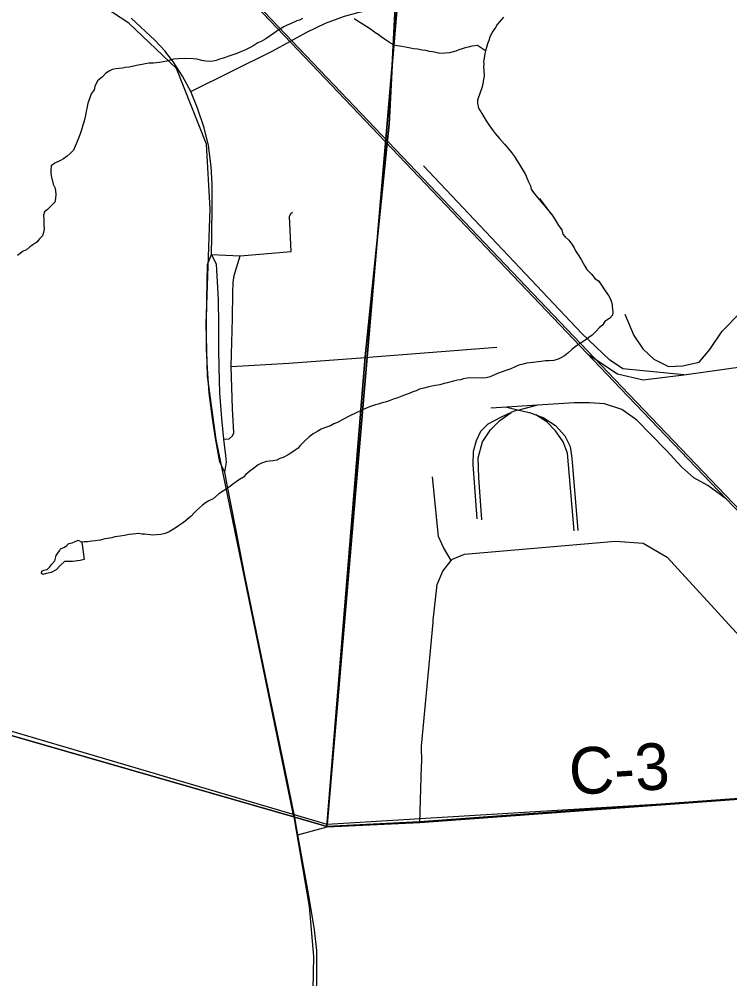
# Model space of a CAD drawing. Extents: x 0 to 34, y 0 to 22.
# Drawn here: x 13.591 to 14.456, y 14.81 to 15.978 of the extents above; entities that cross this region are included whole.
import ezdxf

# ---------------------------------------------------------------- set-up
doc = ezdxf.new("R2010")
doc.units = 0
for name, color, linetype in [('GM_X_City_Street', 7, 'Continuous'), ('GM_X_County_Road', 7, 'Continuous'), ('GM_X_County_Road_Text', 7, 'Continuous'), ('GM_X_Minor_River', 7, 'Continuous'), ('GM_X_Rail_Line', 7, 'Continuous'), ('GM_X_Section', 7, 'Continuous'), ('GM_X_State_Route', 7, 'Continuous'), ('GM_X_Township_Road', 7, 'Continuous'), ('SC_Scratch1', 7, 'Continuous'), ('SH_Cut_Line', 7, 'Continuous')]:
    doc.layers.add(name, color=color, linetype=linetype)

msp = doc.modelspace()

# ---------------------------------------------------------------- linework, layer by layer
at = {"layer": 'GM_X_City_Street'}
for points in [[(13.8248, 15.6914), (13.8596, 15.6897), (13.9219, 15.6948), (13.9199, 15.7377), (13.9214, 15.7411), (13.9234, 15.743)], [(13.84, 15.4669), (13.8462, 15.4673), (13.8503, 15.4706), (13.8521, 15.4746), (13.8503, 15.5039), (13.8489, 15.5549), (13.8506, 15.6134), (13.8507, 15.6453), (13.8514, 15.6574), (13.8526, 15.666), (13.8596, 15.6897)]]:
    msp.add_lwpolyline(points, dxfattribs=at)
at = {"layer": 'GM_X_County_Road'}
msp.add_line((13.9301, 14.9855), (13.9655, 14.995), dxfattribs=at)
for points in [[(13.8997, 15.939), (13.941, 15.9618), (13.9637, 15.9729), (13.9868, 15.9812), (14.0046, 15.9861), (14.0169, 15.9886), (14.0308, 15.9904), (14.0486, 15.9922), (14.137, 15.9987), (14.2945, 16.0126), (14.3436, 16.017)], [(13.7996, 15.8897), (13.8988, 15.9385), (13.8997, 15.939)], [(13.9655, 14.995), (14.0785, 15.0005), (14.5056, 15.0318), (14.9883, 15.0618)]]:
    msp.add_lwpolyline(points, dxfattribs=at)
at = {"layer": 'GM_X_Minor_River'}
for points in [[(13.9355, 15.9783), (13.932, 15.9765), (13.9286, 15.9755), (13.922, 15.9723), (13.917, 15.9705), (13.9128, 15.9684), (13.9062, 15.9644), (13.9016, 15.9611), (13.8965, 15.9575), (13.8911, 15.9538), (13.8853, 15.9506), (13.8811, 15.9488), (13.8764, 15.9455), (13.8726, 15.9437), (13.8656, 15.9398), (13.8614, 15.9384), (13.8556, 15.9359), (13.8521, 15.9345), (13.8483, 15.9335), (13.8449, 15.9324), (13.8406, 15.9307), (13.8345, 15.9289), (13.8307, 15.9275), (13.8268, 15.9265), (13.823, 15.9263), (13.8181, 15.9264), (13.8132, 15.9273), (13.8071, 15.929), (13.8026, 15.9295), (13.7916, 15.9299), (13.784, 15.9293), (13.7786, 15.9288), (13.7706, 15.9267), (13.7614, 15.9251), (13.7542, 15.9242), (13.7488, 15.924), (13.7442, 15.9233), (13.7404, 15.9223), (13.7355, 15.9217), (13.7301, 15.9203), (13.7248, 15.9194), (13.7198, 15.9188), (13.7164, 15.9181), (13.7121, 15.9175), (13.7083, 15.9172), (13.7041, 15.9162), (13.7003, 15.9144), (13.6964, 15.9119), (13.6921, 15.9074), (13.6863, 15.9027), (13.683, 15.8959), (13.6821, 15.8918), (13.6786, 15.8869), (13.6765, 15.8809), (13.6744, 15.8753)], [(14.1586, 15.9392), (14.1489, 15.9456), (14.1417, 15.9446), (14.1375, 15.9436), (14.1336, 15.9426), (14.1302, 15.9416), (14.126, 15.9402), (14.1225, 15.9388), (14.1148, 15.9367), (14.1095, 15.9361), (14.103, 15.9359), (14.0981, 15.9369), (14.094, 15.9377), (14.0902, 15.9382), (14.086, 15.9395), (14.0815, 15.94), (14.0758, 15.941), (14.0709, 15.9415), (14.0671, 15.9424), (14.0611, 15.9437), (14.0565, 15.9442), (14.0509, 15.9451), (14.0475, 15.946), (14.0426, 15.9484), (14.0355, 15.9532), (14.0314, 15.956), (14.0277, 15.9588), (14.0236, 15.9616), (14.0195, 15.9647), (14.0139, 15.9683), (14.0064, 15.9731), (14.002, 15.9759), (13.9986, 15.9779)], [(14.1803, 15.98), (14.1756, 15.9744), (14.1725, 15.9711), (14.1705, 15.9673), (14.1665, 15.9618), (14.1637, 15.9558), (14.1624, 15.9516), (14.1608, 15.9475), (14.1595, 15.943), (14.1586, 15.9392), (14.1578, 15.9358), (14.1568, 15.9301), (14.156, 15.9263), (14.1563, 15.9229), (14.1561, 15.9191), (14.1564, 15.9157), (14.157, 15.9081), (14.1557, 15.9024), (14.1552, 15.8986), (14.1539, 15.8941), (14.1518, 15.8885), (14.1506, 15.8847), (14.1489, 15.8794), (14.1488, 15.8756), (14.1501, 15.8695), (14.1541, 15.8629), (14.1563, 15.859), (14.1592, 15.854), (14.1625, 15.849), (14.1665, 15.8435), (14.1701, 15.8385), (14.1753, 15.8326), (14.1815, 15.8256), (14.1863, 15.8197), (14.19, 15.8154), (14.1936, 15.8104), (14.1962, 15.8065), (14.1991, 15.8022), (14.2016, 15.798), (14.2071, 15.7887), (14.2089, 15.7848), (14.2106, 15.7798), (14.2131, 15.7748), (14.2142, 15.771), (14.2178, 15.7655), (14.2387, 15.7406), (14.2244, 15.7595)], [(13.6744, 15.8753), (13.6736, 15.8711), (13.6722, 15.8651), (13.6714, 15.8609), (13.6705, 15.8568), (13.6696, 15.8522), (13.6683, 15.8485), (13.6671, 15.8443), (13.665, 15.8383), (13.6638, 15.8349), (13.6605, 15.8267), (13.6589, 15.8233), (13.6568, 15.8184), (13.6529, 15.8144), (13.649, 15.811), (13.6447, 15.8078), (13.6401, 15.8052), (13.6343, 15.8024), (13.6296, 15.7991), (13.6291, 15.7942), (13.6294, 15.79), (13.63, 15.7854), (13.632, 15.777), (13.6346, 15.7719), (13.6355, 15.7647), (13.635, 15.7594), (13.6341, 15.7552), (13.6294, 15.7501), (13.6251, 15.746), (13.6216, 15.7431), (13.6203, 15.7393), (13.6209, 15.7336), (13.6207, 15.7271), (13.621, 15.7226), (13.6204, 15.718), (13.6192, 15.7142), (13.6157, 15.7102), (13.6121, 15.7065), (13.6036, 15.7007), (13.5997, 15.697), (13.5958, 15.6952), (13.5888, 15.6901)], [(14.2387, 15.7406), (14.242, 15.7355), (14.2446, 15.7313), (14.2475, 15.7266), (14.2515, 15.7212), (14.2525, 15.7162), (14.2554, 15.7127), (14.2599, 15.7087), (14.2635, 15.7041), (14.2664, 15.6994), (14.2682, 15.6959), (14.2704, 15.6921), (14.2748, 15.6851), (14.2773, 15.6808), (14.2795, 15.677), (14.282, 15.6731), (14.2875, 15.6676), (14.2919, 15.6618), (14.296, 15.6594), (14.2997, 15.6539), (14.3041, 15.6473), (14.3081, 15.6415), (14.3103, 15.638), (14.3124, 15.6326), (14.3129, 15.625), (14.3136, 15.6212), (14.3131, 15.6174), (14.3099, 15.6137), (14.3037, 15.6097), (14.3009, 15.6052), (14.2974, 15.6027), (14.2927, 15.5975), (14.2884, 15.5934), (14.2842, 15.5905), (14.2783, 15.5861), (14.2729, 15.5825), (14.2694, 15.5803), (14.2636, 15.5756), (14.2585, 15.5712), (14.2546, 15.5682), (14.2511, 15.5661), (14.2469, 15.5639), (14.2415, 15.5625), (14.2358, 15.562), (14.2313, 15.5621), (14.2263, 15.5611), (14.2229, 15.5608), (14.216, 15.5599), (14.2126, 15.5596), (14.2087, 15.559), (14.2042, 15.558), (14.1992, 15.5566), (14.1946, 15.5545), (14.1892, 15.5524), (14.1846, 15.5506), (14.18, 15.5492), (14.175, 15.5475), (14.1696, 15.545), (14.1642, 15.5425), (14.1592, 15.5415), (14.1542, 15.5409), (14.1394, 15.5413), (14.136, 15.5411), (14.1318, 15.54), (14.128, 15.539), (14.1245, 15.5384), (14.118, 15.5367), (14.1123, 15.5353), (14.1081, 15.5343), (14.1027, 15.5329), (14.0977, 15.532), (14.0931, 15.531), (14.0893, 15.5303), (14.0832, 15.5286), (14.0782, 15.5276), (14.074, 15.5255), (14.0698, 15.5241), (14.0655, 15.5223), (14.0617, 15.5209), (14.0567, 15.5191), (14.0505, 15.5167), (14.0471, 15.5156), (14.0413, 15.5135), (14.0379, 15.5121), (14.0325, 15.5108), (14.0279, 15.5094), (14.0245, 15.5083), (14.021, 15.5073), (14.0172, 15.5059), (14.0087, 15.5024), (14.0018, 15.4992), (13.9925, 15.4945), (13.9856, 15.4909), (13.979, 15.4873), (13.974, 15.4852), (13.9697, 15.483), (13.9624, 15.4806), (13.9582, 15.4788), (13.9543, 15.4763), (13.9485, 15.473), (13.9439, 15.4694)], [(13.9439, 15.4694), (13.938, 15.4642), (13.9329, 15.4591), (13.9302, 15.4557), (13.9267, 15.4532), (13.9228, 15.4506), (13.9182, 15.4477), (13.912, 15.4445), (13.9081, 15.4431), (13.9043, 15.4413), (13.9001, 15.4403), (13.8955, 15.44), (13.8917, 15.4394), (13.8856, 15.4377), (13.8817, 15.4355), (13.8759, 15.4311), (13.8716, 15.4278), (13.8665, 15.4238), (13.8638, 15.4205), (13.8588, 15.4176), (13.8549, 15.4147), (13.8506, 15.4114), (13.8467, 15.4088), (13.8393, 15.4037), (13.8339, 15.4001), (13.8269, 15.3942), (13.8215, 15.3917), (13.8176, 15.3892), (13.8141, 15.3863), (13.8102, 15.3833), (13.8067, 15.38), (13.8032, 15.3767), (13.8001, 15.373), (13.793, 15.3671), (13.7895, 15.3646), (13.7849, 15.3613), (13.7806, 15.3584), (13.7768, 15.3558), (13.7733, 15.3541), (13.7683, 15.3519), (13.7633, 15.3506), (13.758, 15.3503), (13.7534, 15.3501), (13.7435, 15.3512), (13.7401, 15.3513), (13.7363, 15.3518), (13.7329, 15.3515), (13.7291, 15.3512), (13.7245, 15.3506), (13.7188, 15.3496), (13.7138, 15.3486), (13.7073, 15.3477), (13.7035, 15.3467), (13.6951, 15.3454), (13.6894, 15.3437), (13.6833, 15.3431), (13.6794, 15.3425), (13.6741, 15.3419), (13.6703, 15.342), (13.6672, 15.3412)], [(13.6672, 15.3412), (13.6699, 15.3205), (13.6649, 15.3191), (13.6557, 15.3178), (13.6523, 15.3179), (13.6459, 15.3177), (13.6408, 15.3132), (13.6357, 15.3077), (13.6296, 15.3044), (13.6239, 15.3034), (13.6196, 15.302), (13.6181, 15.3032), (13.6182, 15.3062), (13.6209, 15.3073), (13.6247, 15.3083), (13.6282, 15.3113), (13.6306, 15.3146), (13.6341, 15.3187), (13.6358, 15.3252)], [(13.6358, 15.3252), (13.6397, 15.3308), (13.6409, 15.3334), (13.6459, 15.3352), (13.6486, 15.3374), (13.6513, 15.3396), (13.6552, 15.3406), (13.6625, 15.3439), (13.6672, 15.3412)]]:
    msp.add_lwpolyline(points, dxfattribs=at)
at = {"layer": 'GM_X_Rail_Line'}
for p, q in [((14.1843, 15.5055), (14.1648, 15.5043)), ((14.2219, 15.5079), (14.1843, 15.5055)), ((14.1843, 15.5055), (14.1991, 15.5021)), ((14.2219, 15.5079), (14.1991, 15.5021))]:
    msp.add_line(p, q, dxfattribs=at)
for points in [[(13.9251, 15.0074), (13.8306, 15.4663), (13.8199, 15.5432), (13.8183, 15.6072), (13.8232, 15.7469), (13.8187, 15.8256), (13.7821, 15.9177), (13.7244, 15.9729), (13.613, 16.0458), (13.1693, 16.3287), (13.0295, 16.4167), (12.9545, 16.4717), (12.6624, 16.6978), (12.5258, 16.8003)], [(14.7818, 15.0494), (14.3228, 15.5285), (13.9217, 15.9488), (13.7319, 16.148)], [(14.7846, 15.05), (14.3246, 15.5302), (13.9235, 15.9505), (13.7337, 16.1497)], [(14.4001, 15.5449), (14.3255, 15.5522), (14.3094, 15.5631), (14.2758, 15.5952), (14.083, 15.7994)], [(14.4001, 15.5449), (14.4983, 15.5587), (14.5367, 15.5621), (14.5959, 15.5651), (14.8075, 15.5794), (14.82, 15.5818)], [(14.2832, 15.5701), (14.319, 15.5461), (14.3503, 15.539), (14.4001, 15.5449)], [(14.452, 15.3937), (14.4292, 15.4104), (14.4121, 15.4198), (14.3974, 15.4326), (14.3782, 15.4535), (14.3425, 15.4899), (14.3244, 15.5028), (14.3035, 15.5098), (14.2852, 15.511), (14.2664, 15.5107), (14.2219, 15.5079)], [(14.1897, 15.499), (14.1776, 15.4936), (14.1611, 15.4848), (14.1523, 15.476), (14.1469, 15.4648), (14.1434, 15.4517), (14.1431, 15.4358), (14.1481, 15.3699)], [(14.154, 15.3685), (14.1502, 15.4201), (14.1494, 15.444), (14.1548, 15.4636), (14.1646, 15.478), (14.1757, 15.4894), (14.1897, 15.499)], [(14.1991, 15.5021), (14.1935, 15.5007), (14.1897, 15.499)], [(14.1991, 15.5021), (14.2122, 15.4991), (14.2196, 15.4964)], [(14.2662, 15.3553), (14.2582, 15.4497), (14.2532, 15.4634), (14.2437, 15.4767), (14.233, 15.4876), (14.2196, 15.4964)], [(14.2196, 15.4964), (14.2286, 15.493), (14.2437, 15.4835), (14.2551, 15.4709), (14.2615, 15.4579), (14.2637, 15.4434), (14.271, 15.3555)], [(13.9251, 15.0074), (13.9437, 14.8982), (13.9491, 14.8375), (13.948, 14.7771), (13.9136, 14.3852), (13.8994, 14.3257), (13.8789, 14.2591), (13.872, 14.2266), (13.8727, 14.1891), (13.8776, 14.1566), (13.896, 14.1038), (13.9123, 14.0629), (13.914, 14.0319), (13.9078, 13.9882), (13.8857, 13.7329), (13.8873, 13.679), (13.8962, 13.6329), (13.9115, 13.589), (13.9381, 13.5363), (14.0101, 13.4361)]]:
    msp.add_lwpolyline(points, dxfattribs=at)
at = {"layer": 'GM_X_Section'}
for points in [[(12.9642, 16.3503), (14.0511, 15.9925), (13.9657, 14.9981), (12.8901, 15.3152)], [(15.0788, 16.0806), (14.9863, 15.0601), (13.9657, 14.9981), (14.0511, 15.9925)]]:
    msp.add_lwpolyline(points, close=True, dxfattribs=at)
at = {"layer": 'GM_X_State_Route'}
for p, q in [((13.8311, 15.6794), (13.8248, 15.6914)), ((13.9533, 14.8168), (13.9533, 14.8448))]:
    msp.add_line(p, q, dxfattribs=at)
for points in [[(13.8248, 15.6914), (13.8251, 15.7136), (13.8257, 15.752), (13.8258, 15.777), (13.8244, 15.7985), (13.8211, 15.8239), (13.8158, 15.8455), (13.8079, 15.8692), (13.7996, 15.8897), (13.7897, 15.9081), (13.7787, 15.9255), (13.7679, 15.939), (13.756, 15.9521), (13.7272, 15.979)], [(13.8412, 15.4264), (13.835, 15.4389), (13.8299, 15.4678), (13.8261, 15.4918), (13.8222, 15.5228), (13.8199, 15.5526), (13.819, 15.5761), (13.8188, 15.6057), (13.8192, 15.6365), (13.8199, 15.6792), (13.8248, 15.6914)], [(13.8371, 15.497), (13.8352, 15.523), (13.8342, 15.5534), (13.8338, 15.5766), (13.8337, 15.6057), (13.8335, 15.6364), (13.8311, 15.6794)], [(13.8424, 15.4468), (13.84, 15.4669), (13.8375, 15.492), (13.8371, 15.497)], [(13.8412, 15.4264), (13.8433, 15.4387), (13.8424, 15.4468)], [(13.8975, 15.1457), (13.883, 15.2163), (13.865, 15.3027), (13.8544, 15.3576), (13.8437, 15.413), (13.8412, 15.4264)], [(13.9264, 15.0063), (13.9145, 15.064), (13.8983, 15.1417), (13.8975, 15.1457)], [(13.945, 14.9017), (13.9419, 14.9205), (13.9301, 14.9855), (13.9264, 15.0063)], [(13.9533, 14.8448), (13.9502, 14.8698), (13.945, 14.9017)], [(13.9465, 14.7318), (13.9533, 14.8047), (13.9533, 14.8168)]]:
    msp.add_lwpolyline(points, dxfattribs=at)
at = {"layer": 'GM_X_Township_Road'}
for p, q in [((14.0211, 15.5669), (14.1724, 15.5788)), ((14.0785, 15.0005), (14.0807, 15.069))]:
    msp.add_line(p, q, dxfattribs=at)
for points in [[(14.3281, 15.6186), (14.3391, 15.5928), (14.3499, 15.5765), (14.3632, 15.5639), (14.3811, 15.5553), (14.3982, 15.5561), (14.4185, 15.5605), (14.4315, 15.5758), (14.4467, 15.5979), (14.4686, 15.6203), (14.4815, 15.6255), (14.5128, 15.6295), (14.5218, 15.6316), (14.5494, 15.6414), (14.7545, 15.7562), (14.8005, 15.7656), (14.8846, 15.7644)], [(13.8489, 15.5549), (13.919, 15.5593), (14.012, 15.5662), (14.0211, 15.5669)], [(14.1168, 15.3191), (14.1072, 15.3349), (14.1014, 15.3483), (14.094, 15.421)], [(14.0807, 15.069), (14.0809, 15.0739), (14.0806, 15.0934), (14.0946, 15.2437), (14.0949, 15.2467), (14.0998, 15.2899), (14.1064, 15.306), (14.1168, 15.3191), (14.1183, 15.3209), (14.1329, 15.3269), (14.3167, 15.3426), (14.3504, 15.34), (14.3795, 15.3232), (14.4994, 15.1924), (14.5084, 15.177), (14.5037, 15.0635), (14.5044, 15.0516)]]:
    msp.add_lwpolyline(points, dxfattribs=at)
at = {"layer": 'SC_Scratch1'}
for points in [[(14.0483, 15.9927), (14.0411, 15.8502), (14.0118, 15.5668), (13.9652, 14.9956), (14.0783, 15.001), (14.5054, 15.0324), (14.9881, 15.0623), (15.1228, 15.0411), (15.3254, 15.0063), (15.5154, 14.9734), (15.5826, 14.9621), (15.7547, 14.933), (15.8407, 14.9188), (15.9769, 14.894), (16.1, 14.8738), (16.1, 19.8941)], [(11.871, 15.1527), (12.8889, 15.308), (12.9952, 15.2762), (13.1413, 15.2326), (13.9262, 15.0068), (13.9652, 14.9956), (14.0118, 15.5668), (14.0411, 15.8502), (14.0483, 15.9927)], [(15.1228, 15.0411), (14.9881, 15.0623), (14.5054, 15.0324), (14.0783, 15.001), (13.9652, 14.9956), (13.9262, 15.0068), (13.1413, 15.2326), (12.9952, 15.2762), (12.8889, 15.308), (11.871, 15.1527)]]:
    msp.add_lwpolyline(points, dxfattribs=at)
at = {"layer": 'SH_Cut_Line'}
for points in [[(11.871, 15.1527), (12.8889, 15.308), (12.9952, 15.2762), (13.1413, 15.2326), (13.9262, 15.0068), (13.9652, 14.9956), (14.0783, 15.001), (14.5054, 15.0324), (14.9881, 15.0623), (15.1228, 15.0411), (15.3254, 15.0063), (15.5154, 14.9734), (15.5826, 14.9621), (15.7547, 14.933), (15.8407, 14.9188), (15.9769, 14.894), (16.1, 14.8738), (16.1, 20.2361)], [(9.3, 13.4361), (16.1, 13.4361), (16.1, 14.8738), (15.9769, 14.894), (15.8407, 14.9188), (15.7547, 14.933), (15.5826, 14.9621), (15.5154, 14.9734), (15.3254, 15.0063), (15.1228, 15.0411), (14.9881, 15.0623), (14.5054, 15.0324), (14.0783, 15.001), (13.9652, 14.9956), (13.9262, 15.0068), (13.1413, 15.2326), (12.9952, 15.2762), (12.8889, 15.308), (11.871, 15.1527)]]:
    msp.add_lwpolyline(points, dxfattribs=at)

# ---------------------------------------------------------------- texts
at = {"layer": 'GM_X_County_Road_Text'}
msp.add_text('C-3', height=0.05682, rotation=3.5027, dxfattribs=at).set_placement((14.2617, 15.0338))

doc.saveas('drawing.dxf')
